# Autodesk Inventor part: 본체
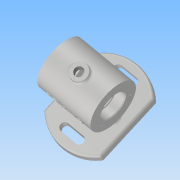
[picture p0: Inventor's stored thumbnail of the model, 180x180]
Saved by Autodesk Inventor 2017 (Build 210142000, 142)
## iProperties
Part Number: 본체
Material: 알루미늄 6061
Document SubType Name: Modeling
Designer: user
Density: 2.7 g/cm^3
Appearance: 알루미늄 - 평지
Mass: 467.937 g
Surface Area: 487.008 cm^2
Volume: 173.31 cm^3
Author: user
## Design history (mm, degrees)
sketch "스케치1"
  geometry: C1 r 30 at (0, 0); 1 further point
  constraints: 1 centre point, 1 coincident
  dimensions: "d0" = 60 diameter of C1
extrude "돌출1" new body sketch "스케치1" distance "d1" = 70; taper "d2" = 0 deg
node "작업 평면1"
sketch "스케치3"
  geometry: L1 (0, -30)-(70, -30) reference; L2 (35, -30)-(35, 46.791); L3 (0, 0)-(92.901, 0); L4 (72.5, -36.742)-(72.5, 36.742); L5 (-2.5, -36.742)-(-2.5, 36.742); L6 (45, -37)-(25, -37); L7 (45, -42)-(25, -42); L8 (25, -32)-(45, -32); L9 (45, 42)-(25, 42); L10 (25, 32)-(45, 32); A1 r 52.5 centre (35, 0) between (72.5, 36.742) and (-2.5, 36.742); A2 r 52.5 centre (35, 0) between (-2.5, -36.742) and (72.5, -36.742); A3 r 5 centre (45, -37) between (45, -42) and (45, -32); A4 r 5 centre (25, -37) between (25, -32) and (25, -42); A5 r 5 centre (25, 37) between (25, 42) and (25, 32); A6 r 5 centre (45, 37) between (45, 32) and (45, 42); 1 further point
  constraints: 20 end point, 12 point on circle, 6 centre point, 6 symmetric about line, 4 tangent, 3 point on line, 2 midpoint, 2 parallel, 1 horizontal, 1 perpendicular, 1 vertical, 2 other
  dimensions: "d5" = 37.5 distance between parallel lines of L2 L4; "d6" = 52.5 radius of A2; "d7" = 73.48469 distance of L5.start L5.end; "d8" = 52.5 radius of A1; "d10" = 20 distance of L6.start L6.end; "d11" = 5 radius of A3; "d12" = 37 distance of A1.centre point (35, -37); "d13" = 36.74235 vertical distance of A1.centre L5.start
extrude "돌출2" join sketch "스케치3" distance "d14" = 10; taper "d15" = 0 deg
sketch "스케치4"
  geometry: L1 (-45, -32)-(-25, -32) reference; L2 (-25, -42)-(-45, -42) reference; L3 (-25, 32)-(-45, 32) reference; L4 (-45, 42)-(-25, 42) reference; L5 (-72.5, 36.742)-(-72.5, -36.742) reference; L6 (2.5, -36.742)-(2.5, 36.742) reference; A1 r 5 centre (-45, -37) between (-45, -32) and (-45, -42) reference; A2 r 5 centre (-25, -37) between (-25, -42) and (-25, -32) reference; A3 r 5 centre (-25, 37) between (-25, 32) and (-25, 42) reference; A4 r 5 centre (-45, 37) between (-45, 42) and (-45, 32) reference; A5 r 52.5 centre (-35, 0) between (-72.5, -36.742) and (2.5, -36.742) reference; A6 r 52.5 centre (-35, 0) between (2.5, 36.742) and (-72.5, 36.742) reference; 1 further point
sketch "스케치5"
  geometry: L1 (-72.5, 36.742)-(-72.5, -36.742) reference; L2 (2.5, -36.742)-(2.5, 36.742) reference; L3 (2.5, 0)-(-72.5, 0); L4 (-60, 5)-(-10, 5); L5 (-10, 5)-(-10, -5); L6 (-10, -5)-(-60, -5); L7 (-60, -5)-(-60, 5); L8 (-60, 5)-(-10, -5); L9 (-10, 5)-(-60, -5); A1 r 52.5 centre (-35, 0) between (2.5, 36.742) and (-72.5, 36.742) reference; 1 further point
  constraints: 14 end point, 4 midpoint, 2 parallel, 1 horizontal, 1 perpendicular
  dimensions: "d16" = 50 distance of L5.end L6.end; "d17" = 10 distance of L4.end L5.end
extrude "돌출3" join sketch "스케치5" stored distance "d18" = 10; taper "d19" = 0 deg
fillet "모깎기1" dims "d20" = 3
fillet "모깎기2" dims "d21" = 3
fillet "모깎기3" dims "d22" = 3
fillet "모깎기4" dims "d23" = 3
node "작업 평면2"
sketch "스케치6"
  geometry: C1 r 10 at (35, 0); 2 further points
  constraints: 1 centre point, 1 coincident, 1 horizontal alignment
  dimensions: "d25" = 35 distance of point (0, 0) point (35, 0); "d26" = 20 diameter of C1
extrude "돌출4" join sketch "스케치6" stored distance "d27" = 10; taper "d28" = 0 deg
sketch "스케치7"
  geometry: C1 r 10 at (0, 0) reference; 1 further point
hole "구멍1" sketch "스케치7" at (0, 0) diameter "d29" = 10.917; stored, may be unused: countersink angle "d33" = 90 deg, drill point angle "d35" = 118 deg; dims "d30" = 24, "d31" = 4, "d32" = 2, "d34" = 29.1
fillet "모깎기5" dims "d36" = 3
sketch "스케치9"
  geometry: C1 r 30 at (0, 0) reference; C2 r 16 at (0, 0)
  constraints: 1 centre point, 1 coincident
  dimensions: "d37" = 32 diameter of C2
extrude "돌출5" cut sketch "스케치9" distance "d38" = 12; taper "d39" = 0 deg
sketch "스케치10"
  geometry: C1 r 16 at (0, 0) reference; C2 r 14 at (0, 0)
  constraints: 1 centre point, 1 coincident
  dimensions: "d40" = 28 diameter of C2
extrude "돌출6" cut sketch "스케치10" distance "d41" = 3; taper "d42" = 0 deg
sketch "스케치11"
  geometry: C1 r 14 at (0, 0) reference; C2 r 25 at (0, 0)
  constraints: 1 centre point, 1 coincident
  dimensions: "d43" = 50 diameter of C2
extrude "돌출7" cut sketch "스케치11" distance "d44" = 40; taper "d45" = 0 deg
sketch "스케치12"
  geometry: C1 r 25 at (0, 0) reference; C2 r 14 at (0, 0)
  constraints: 1 centre point, 1 coincident
  dimensions: "d46" = 28 diameter of C2
extrude "돌출8" cut sketch "스케치12" distance "d47" = 3; taper "d48" = 0 deg
sketch "스케치13"
  geometry: C1 r 14 at (0, 0) reference; C2 r 16 at (0, 0)
  constraints: 1 centre point, 1 coincident
  dimensions: "d49" = 32 diameter of C2
extrude "돌출9" cut sketch "스케치13" distance "d50" = 12; taper "d51" = 0 deg
chamfer "모따기1" distance "d52" = 1; stored, may be unused: second distance "d53" = 2, angle "d54" = 45 deg
fillet "모깎기6" dims "d55" = 3
fillet "모깎기7" dims "d56" = 0.3
fillet "모깎기8" dims "d57" = 0.3
sketch "스케치14" dims "d58" = 46
  geometry: C1 r 17 at (0, 0) reference; 2 further points
  constraints: 1 coincident, 1 vertical alignment, 2 other
hole "구멍2" sketch "스케치14" at (0, 23) diameter "d59" = 3.242; stored, may be unused: countersink angle "d63" = 90 deg, drill point angle "d65" = 118 deg; dims "d60" = 8, "d61" = 4, "d62" = 2, "d64" = 10
node "작업 평면3"
node "작업 평면4"
sketch "스케치15"
  geometry: L1 (0, 30)-(-70, 30) reference; L2 (-70, 30)-(-70, -30) reference; 2 further points
  constraints: 1 other
  dimensions: "d70" = 30 distance from line of L1 point (-35, 0); "d71" = 35 distance from line of L2 point (-35, 0)
feature "엠보싱1" sketch "스케치15" dims "d72" = 0.5, "d73" = 0
node "솔리드1"
pattern_circular "원형 패턴1" dims angle "d67" = 360 deg
mirror "미러1"
other parameters: "d3" = -62, "d4" = 105, "d24" = 33, "d69" = 54.25
